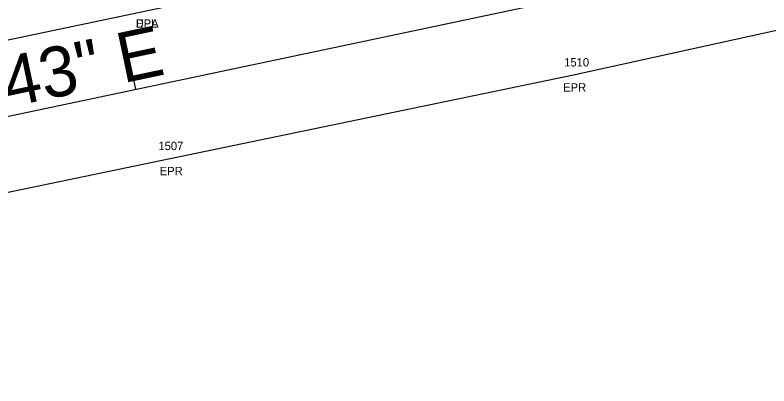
# Model space of a CAD drawing. Extents: x 1965304 to 1970247, y 1117014 to 1118201.
# Drawn here: x 1966562.7 to 1966652.9, y 1117363.8 to 1117408.1 of the extents above; entities that cross this region are included whole.
import ezdxf

# ---------------------------------------------------------------- set-up
doc = ezdxf.new("R2010")
doc.units = 0
for name, color, linetype in [('RD_EX_Driveway_txCode', 7, 'Continuous'), ('RD_EX_Road', 7, 'Continuous'), ('RD_EX_Road_txCode', 7, 'Continuous'), ('RD_HC_Cl', 7, 'Continuous'), ('RD_HC_Data', 7, 'Continuous'), ('RD_HC_Data_Tic', 7, 'Continuous'), ('RD_SMD_Locator', 7, 'Continuous')]:
    doc.layers.add(name, color=color, linetype=linetype)

msp = doc.modelspace()

# ---------------------------------------------------------------- linework, layer by layer
at = {"layer": 'RD_EX_Road'}
for points in [[(1966031.823, 1117232.956), (1966074.66, 1117252.15), (1966117.782, 1117271.581), (1966161.06, 1117290.483), (1966205.406, 1117309.226), (1966251.249, 1117327.393), (1966297.245, 1117343.102), (1966344.085, 1117357.038), (1966390.785, 1117368.561), (1966438.122, 1117379.082), (1966484.547, 1117389.131), (1966531.199, 1117398.733), (1966578.388, 1117408.593), (1966604.527, 1117414.058), (1966624.537, 1117418.323), (1966671.319, 1117428.348), (1966716.506, 1117439.32), (1966736.604, 1117445.59), (1966754.133, 1117451.442), (1966759.658, 1117453.517), (1966769.512, 1117457.475)], [(1965729.992, 1117080.297), (1965819.77, 1117119.134), (1965907.737, 1117159.312), (1965995.365, 1117199.039), (1966039.268, 1117218.497), (1966081.241, 1117237.148), (1966124.666, 1117256.555), (1966167.659, 1117275.555), (1966211.467, 1117293.627), (1966257.791, 1117311.581), (1966302.7, 1117327.207), (1966347.903, 1117339.982), (1966394.806, 1117351.637), (1966441.557, 1117361.865), (1966488.625, 1117372.057), (1966534.906, 1117381.34), (1966581.234, 1117390.947), (1966629.533, 1117400.947), (1966675.632, 1117411.107), (1966721.676, 1117422.847), (1966766.802, 1117438.972), (1966775.751, 1117440.571)]]:
    msp.add_lwpolyline(points, dxfattribs=at)
at = {"layer": 'RD_HC_Cl'}
msp.add_line((1966425.261, 1117367.215), (1966684.871, 1117421.945), dxfattribs=at)
at = {"layer": 'RD_HC_Data_Tic'}
msp.add_line((1966577.124, 1117399.23), (1966576.299, 1117403.144), dxfattribs=at)
at = {"layer": 'RD_SMD_Locator'}
for centre in [(1966629.533, 1117400.947), (1966629.533, 1117400.947), (1966581.234, 1117390.947), (1966581.234, 1117390.947)]:
    msp.add_circle(centre, 0.001, dxfattribs=at)

# ---------------------------------------------------------------- texts
at = {"layer": 'RD_EX_Driveway_txCode'}
msp.add_text('DPA', height=1, dxfattribs=at).set_placement((1966577.12, 1117406.593))
msp.add_text('DPA', height=1, dxfattribs=at).set_placement((1966577.12, 1117406.593))
at = {"layer": 'RD_EX_Road_txCode'}
for s, p in [('EPL', (1966577.183, 1117406.593)), ('EPL', (1966577.183, 1117406.593)), ('1510', (1966628.43, 1117401.947)), ('1510', (1966628.43, 1117401.947)), ('EPR', (1966628.304, 1117398.947)), ('EPR', (1966628.304, 1117398.947)), ('1507', (1966579.848, 1117391.947)), ('1507', (1966579.848, 1117391.947)), ('EPR', (1966580.006, 1117388.947)), ('EPR', (1966580.006, 1117388.947))]:
    msp.add_text(s, height=1, dxfattribs=at).set_placement(p)
at = {"layer": 'RD_HC_Data'}
msp.add_text('N 78%%d 05\' 43" E', height=6, rotation=11.90472, dxfattribs=at).set_placement((1966527.578, 1117389.807))

doc.saveas('drawing.dxf')
